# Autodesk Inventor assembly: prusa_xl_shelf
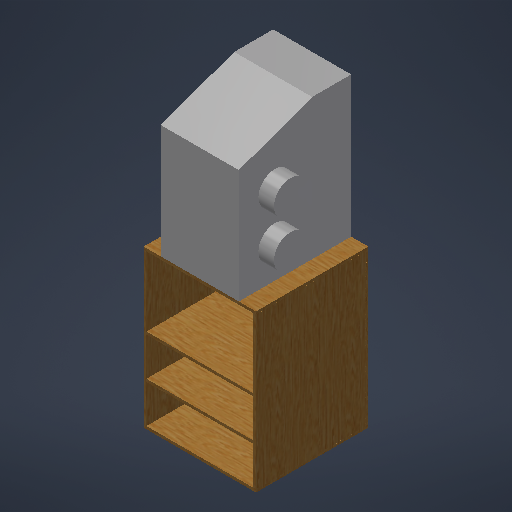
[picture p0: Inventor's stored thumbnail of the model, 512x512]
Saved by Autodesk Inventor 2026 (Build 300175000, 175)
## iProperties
Created: 2025-03
Part Number: prusa_xl_shelf
Material: Generisch
Document SubType Name: Assembly
Designer: BennF
Author: BennF
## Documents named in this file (8)
- C:\Users\BennF\Nextcloud\Benedikt\Unikat\CAD\Drucker_regal\prusa_xl_shelf.iam
- C:\Users\BennF\Nextcloud\Benedikt\Unikat\CAD\Drucker_regal\Prusa_XL_enclosure.ipt
- C:\Users\BennF\Nextcloud\Benedikt\Unikat\CAD\Drucker_regal\prusa_xl_shelf.ipt
- C:\Users\BennF\Nextcloud\Benedikt\Unikat\CAD\Drucker_regal\prusa_xl_left_side.ipt
- C:\Users\BennF\Nextcloud\Benedikt\Unikat\CAD\Drucker_regal\prusa_xl_top_plate.ipt
- C:\Users\BennF\Nextcloud\Benedikt\Unikat\CAD\Drucker_regal\prusa_xl_back_panel.ipt
- C:\Users\BennF\Nextcloud\Benedikt\Unikat\CAD\Drucker_regal\prusa_xl_right_side.ipt
- C:\Users\BennF\Nextcloud\Benedikt\Unikat\CAD\Drucker_regal\prusa_xl_bottom_plate.ipt
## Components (8 placed, 7 different names)
1. prusa_xl_enclosure:1 — Flush:11, Mate:14, Mate:15
2. prusa_xl_bottom_plate:1 — Flush:1, Mate:1, Flush:2, Flush:3, Flush:4, Mate:2, Mate:13, Flush:16, Flush:17
3. prusa_xl_top_plate:1 — Flush:5, Flush:15, Mate:3, Mate:14, Mate:15
4. prusa_xl_shelf:1 — Flush:7, Flush:13, Mate:6, Mate:9
5. prusa_xl_shelf:2 — Flush:8, Flush:14, Mate:7, Mate:8
6. prusa_xl_left_side:1 — Flush:1, Mate:1, Flush:2, Flush:5, Flush:7, Flush:8, Flush:13, Flush:14, Mate:6, Mate:7, Mate:8, Mate:9, Mate:3
7. prusa_xl_right_side:1 — Flush:3, Flush:4, Mate:2, Flush:15
8. prusa_xl_back_panel:1 — Mate:13, Flush:16, Flush:17, Flush:11
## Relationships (23: Flush 13, Mate 10)
- Flush:1: prusa_xl_bottom_plate:1 ↔ prusa_xl_left_side:1
- Mate:1: prusa_xl_bottom_plate:1 ↔ prusa_xl_left_side:1
- Flush:2: prusa_xl_bottom_plate:1 ↔ prusa_xl_left_side:1
- Flush:3: prusa_xl_bottom_plate:1 ↔ prusa_xl_right_side:1
- Flush:4: prusa_xl_bottom_plate:1 ↔ prusa_xl_right_side:1
- Mate:2: prusa_xl_bottom_plate:1 ↔ prusa_xl_right_side:1
- Flush:5: prusa_xl_top_plate:1 ↔ prusa_xl_left_side:1
- Flush:15: prusa_xl_top_plate:1 ↔ prusa_xl_right_side:1
- Mate:3: prusa_xl_top_plate:1 ↔ prusa_xl_left_side:1
- Flush:7: prusa_xl_shelf:1 ↔ prusa_xl_left_side:1
- Flush:8: prusa_xl_shelf:2 ↔ prusa_xl_left_side:1
- Mate:13: prusa_xl_bottom_plate:1 ↔ prusa_xl_back_panel:1
- Flush:16: prusa_xl_bottom_plate:1 ↔ prusa_xl_back_panel:1
- Flush:17: prusa_xl_bottom_plate:1 ↔ prusa_xl_back_panel:1
- Flush:11: prusa_xl_enclosure:1 ↔ prusa_xl_back_panel:1
- Flush:13: prusa_xl_shelf:1 ↔ prusa_xl_left_side:1
- Flush:14: prusa_xl_shelf:2 ↔ prusa_xl_left_side:1
- Mate:6: prusa_xl_shelf:1 ↔ prusa_xl_left_side:1
- Mate:7: prusa_xl_shelf:2 ↔ prusa_xl_left_side:1
- Mate:8: prusa_xl_shelf:2 ↔ prusa_xl_left_side:1
- Mate:9: prusa_xl_shelf:1 ↔ prusa_xl_left_side:1
- Mate:14: prusa_xl_enclosure:1 ↔ prusa_xl_top_plate:1
- Mate:15: prusa_xl_enclosure:1 ↔ prusa_xl_top_plate:1
